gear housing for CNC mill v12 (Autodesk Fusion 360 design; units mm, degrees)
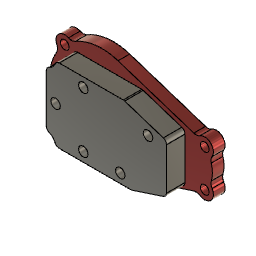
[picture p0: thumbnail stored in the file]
description: Gear Housing Assembly
derived_base_feature "Derived Base Feature1"
derived_base_feature "Derived Base Feature1" bodies "Front Housing"
derived_base_feature "Derived Base Feature1" bodies "Front Cover"
derived_base_feature "Derived Base Feature1" bodies "Back Housing"
as_built_joint "As-built1"
offset_faces "OffsetFaces1" distance 5
delete_face "DeleteFace1"
delete_face "DeleteFace2"
sketch "Sketch1" plane through (0, -21, 0) normal (0, -1, 0) x axis (1, 0, 0)
  line L1 (11.1724, 34.2225) -> (63.2283, 17.2281)
  line L2 (63.2283, -17.2281) -> (11.1724, -34.2225)
  arc A1 centre (64.7801, 21.9812) radius 5 clockwise from (67.4836, 17.7752) to (63.2283, 17.2281)
  arc A2 centre (0, 0) radius 36 clockwise from (-18.189, 31.067) to (11.1724, 34.2225)
  arc A3 centre (-20.7152, 35.3819) radius 5 clockwise from (-18.189, 31.067) to (-22.8701, 30.8701)
  arc A4 centre (-25.4558, 25.4558) radius 6 clockwise from (-30.8701, 22.8701) to (-22.8701, 30.8701)
  arc A5 centre (-35.3819, 20.7152) radius 5 clockwise from (-30.8701, 22.8701) to (-31.067, 18.189)
  arc A6 centre (0, 0) radius 36 clockwise from (-31.067, -18.189) to (-31.067, 18.189)
  arc A7 centre (-35.3819, -20.7152) radius 5 clockwise from (-31.067, -18.189) to (-30.8701, -22.8701)
  arc A8 centre (-25.4558, -25.4558) radius 6 clockwise from (-22.8701, -30.8701) to (-30.8701, -22.8701)
  arc A9 centre (-20.7152, -35.3819) radius 5 clockwise from (-22.8701, -30.8701) to (-18.189, -31.067)
  arc A10 centre (0, 0) radius 36 clockwise from (11.1724, -34.2225) to (-18.189, -31.067)
  arc A11 centre (64.7801, -21.9812) radius 5 clockwise from (63.2283, -17.2281) to (67.4836, -17.7752)
  arc A12 centre (70.7279, -12.7279) radius 6 clockwise from (75.774, -9.4818) to (67.4836, -17.7752)
  arc A13 centre (79.979, -6.7767) radius 5 clockwise from (75.774, -9.4818) to (75.201, -5.3035)
  arc A14 centre (58, 0) radius 18 clockwise from (75.201, 5.3035) to (75.201, -5.3035)
  arc A15 centre (79.979, 6.7767) radius 5 clockwise from (75.201, 5.3035) to (75.774, 9.4818)
  arc A16 centre (70.7279, 12.7279) radius 6 clockwise from (67.4836, 17.7752) to (75.774, 9.4818)
  circle C1 centre (70.7279, -12.7279) radius 3
  circle C2 centre (70.7279, 12.7279) radius 3
  circle C3 centre (-25.4558, -25.4558) radius 3
  circle C4 centre (-25.4558, 25.4558) radius 3
  circle C5 centre (0, 0) radius 5.25
  circle C6 centre (0, 0) radius 19.05
  point P1 (0, 0)
  point P34 (0, 0)
  point P35 (0, -19.05)
  point P36 (-19.05, 0)
  point P37 (0, 19.05)
  point P38 (44.45, 12.7)
  point P39 (25.4, -19.05)
  coincident P1 P34
  coincident C6 P35
  coincident C6 P36
  coincident C6 P37
  vertical P34 P35
  horizontal P1 P36
  vertical P1 P37
  dimension "d2" diameter C6 = 38.1
  dimension "d3" distance P1 P38 = 44.45
  dimension "d4" distance P1 P38 = 12.7
  dimension "d5" distance P34 P39 = 25.4
  dimension "d6" distance P34 P39 = 19.05
hole "Hole1" HoleDepth 5.715 HoleDiameter 5.1308 TipAngle 118
ground "Ground1"
ground "Ground2"
ground "Ground3"
ground "Ground4"
position "Position1"
sketch "Sketch1" plane through (0, 0, 0) normal (0, 1, 0) x axis (1, 0, 0)
  line L1 (57.15, -25.4) -> (-25.4, -25.4)
  line L2 (57.15, 25.4) -> (57.15, -25.4)
  line L3 (-25.4, 25.4) -> (57.15, 25.4)
  line L4 (-25.4, -25.4) -> (-25.4, 25.4)
  line L5 (11.1724, -34.2225) -> (63.2283, -17.2281)
  line L6 (63.2283, 17.2281) -> (11.1724, 34.2225)
  line L7 (10.1871, -31.2042) -> (62.243, -14.2098)
  line L8 (62.7357, 15.719) -> (10.6797, 32.7134)
  circle C1 centre (-25.4558, -25.4558) radius 3
  circle C2 centre (-25.4558, 25.4558) radius 3
  circle C3 centre (-25.4558, -25.4558) radius 6.35
  circle C4 centre (-25.4558, 25.4558) radius 6.35
  point P1 (0, 0)
  horizontal L1
  vertical L2
  horizontal L3
  vertical L4
  concentric C1 C3
  concentric C2 C4
  equal C3 C4
  dimension "d10" distance P1 L1 = 25.4
  dimension "d11" distance P1 L3 = 25.4 (= "d10")
  dimension "d12" distance P1 L2 = 57.15
  dimension "d13" distance P1 L4 = 25.4
  dimension "d14" diameter C3 = 12.7
  dimension "d15" = 3.175
  dimension "d16" = 1.5875
extrude "Extrude1" new body sketch "Sketch1" profile of L1 L2 L3 L4 C3 C4 L7 L8 against normal blind 12.7
fillet "Fillet1" radius 3.175
hole "Hole1" HoleDepth 12.7 HoleDiameter 6.477 TipAngle 118
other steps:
thread "Thread1"
create_component "CreateComponent1"
create_component "CreateComponent5"
create_component "CreateComponent1"
create_component "CreateComponent2"
create_component "CreateComponent3"
named bodies: "Back Housing", "Front Cover", "Front Housing"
